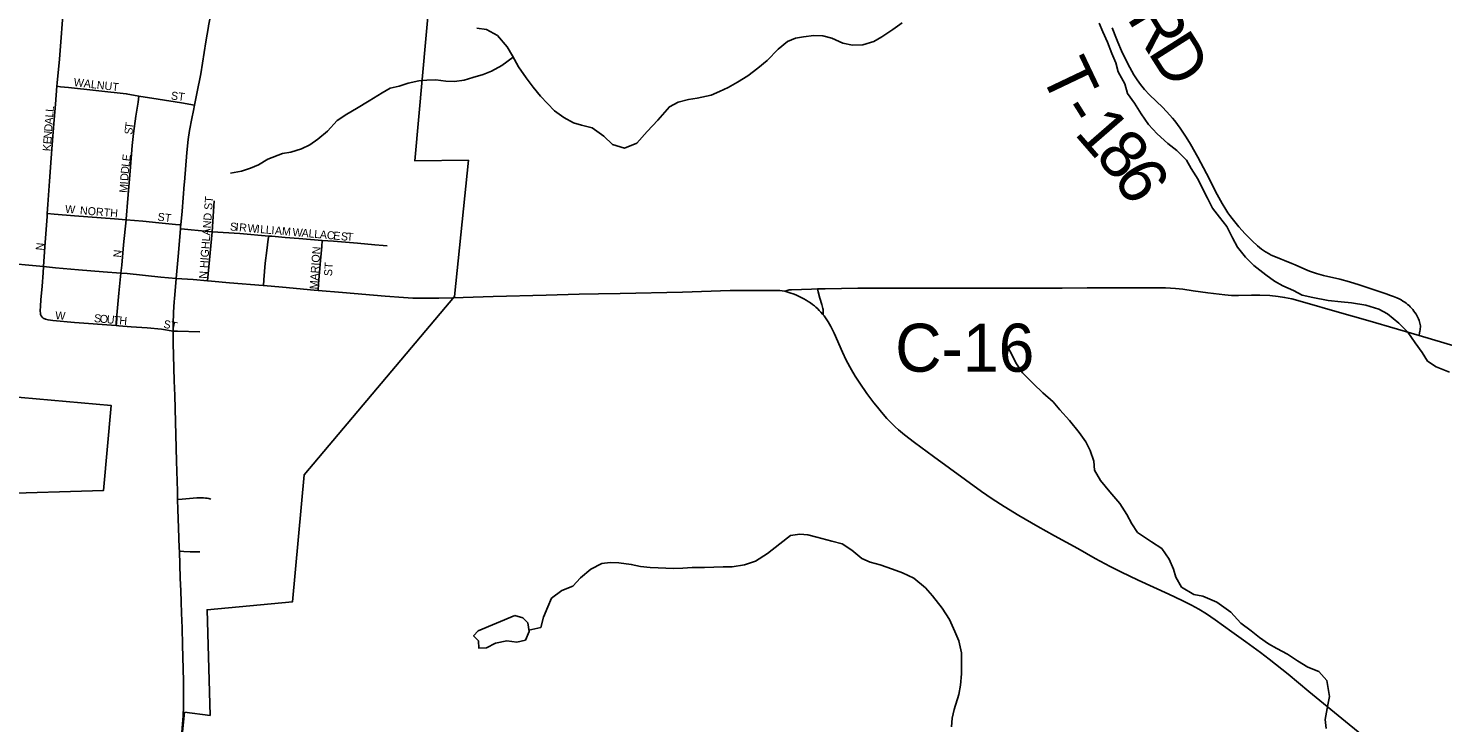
# Model space of a CAD drawing. Extents: x 1451455 to 1749751, y 218250 to 574981.
# Drawn here: x 1601082 to 1609917, y 315557 to 319894 of the extents above; entities that cross this region are included whole.
import ezdxf

# ---------------------------------------------------------------- set-up
doc = ezdxf.new("R2010")
doc.units = 0
for name, color, linetype in [('GM_X_City_Street', 7, 'Continuous'), ('GM_X_City_Street_Text', 7, 'Continuous'), ('GM_X_Corporation', 7, 'Continuous'), ('GM_X_County_Road', 7, 'Continuous'), ('GM_X_County_Road_Text', 7, 'Continuous'), ('GM_X_Minor_Lake', 7, 'Continuous'), ('GM_X_Minor_River', 7, 'Continuous'), ('GM_X_State_Route', 7, 'Continuous'), ('GM_X_Township_Road', 7, 'Continuous'), ('GM_X_Township_Road_Text', 7, 'Continuous'), ('GM_X_US_Route', 7, 'Continuous')]:
    doc.layers.add(name, color=color, linetype=linetype)

msp = doc.modelspace()

# ---------------------------------------------------------------- linework, layer by layer
at = {"layer": 'GM_X_City_Street'}
for points in [[(1601260.7, 319531.9), (1601262.4, 319553.9), (1601276.3, 319702.3), (1601303.8, 320055.2), (1601304.3, 320073.5)], [(1601200.4, 318737.8), (1601204.4, 318793.1), (1601213.7, 318940.3), (1601225, 319084.1), (1601231.1, 319165.9), (1601241.8, 319300), (1601252.3, 319420.9), (1601260.7, 319531.9)], [(1601260.7, 319531.9), (1601282.9, 319529.5), (1601331.8, 319524.3), (1601693, 319485.2), (1601772.9, 319469.7)], [(1601692, 318698.4), (1601692.4, 318702.3), (1601703.3, 318832.1), (1601717.9, 319001.6), (1601731, 319161.4), (1601738.7, 319236.3), (1601753.3, 319346.4), (1601767.2, 319433.7), (1601772.9, 319469.7)], [(1601772.9, 319469.7), (1601892.8, 319450.7), (1602038.4, 319427.9), (1602120.8, 319415.1)], [(1602230.9, 318622.8), (1602243.1, 318817.6)], [(1601176.6, 318405.7), (1601185.2, 318528.4), (1601199, 318717.9), (1601200.4, 318737.8)], [(1601200.4, 318737.8), (1601243.8, 318734.2), (1601369.4, 318723.7), (1601619.8, 318704.9), (1601692, 318698.4)], [(1601659.7, 318364.9), (1601663.6, 318398.3), (1601665.5, 318414.6), (1601676.1, 318541.6), (1601692, 318698.4)], [(1601692, 318698.4), (1601796.6, 318689), (1601897.2, 318679.5), (1602001.5, 318669.1), (1602033.6, 318665.9)], [(1602031.6, 318642.4), (1602057.4, 318640), (1602099.5, 318636.2), (1602230.9, 318622.8)], [(1602201.5, 318316.9), (1602230.9, 318622.8)], [(1602230.9, 318622.8), (1602402.2, 318612.1), (1602583.8, 318596.8)], [(1602550.5, 318287.8), (1602553.5, 318323.3), (1602562.1, 318427.6), (1602571.1, 318505.6), (1602581, 318576.9), (1602583.8, 318596.8)], [(1602583.8, 318596.8), (1602602.4, 318595.2), (1602687.3, 318588.6), (1602772.2, 318580.7), (1602917.9, 318569.4)], [(1602891.9, 318257.4), (1602895.2, 318297.2), (1602907.4, 318444.1), (1602914.8, 318532), (1602917.9, 318569.4)], [(1602917.9, 318569.4), (1602988.9, 318564), (1603088.8, 318556.1), (1603137.7, 318552.2), (1603245.4, 318541.8), (1603297.6, 318537.5), (1603323.7, 318535)], [(1601175, 318083.9), (1601167.6, 318090), (1601161.8, 318097.9), (1601158, 318106.9), (1601156.8, 318113.3), (1601155.9, 318129.3), (1601156.9, 318158.5), (1601160.1, 318197.7), (1601167.6, 318284.3), (1601173.7, 318366.9), (1601176.6, 318405.7)], [(1601630, 318037.4), (1601631.3, 318056.5), (1601633, 318079.5), (1601634.5, 318103), (1601647.3, 318240.2), (1601659.7, 318364.9)], [(1601175, 318083.9), (1601189.3, 318077.4), (1601205.1, 318073.2), (1601234, 318068.5), (1601370.7, 318056.1), (1601630, 318037.4)], [(1601630, 318037.4), (1601646.7, 318036.2), (1601724.9, 318030), (1601823.9, 318023.2), (1601912.9, 318014.4), (1601986.5, 318003.2)], [(1601986.5, 318003.2), (1602013.5, 318002.5), (1602152.3, 317999.1)], [(1602014.5, 316951.9), (1602042.4, 316954.1), (1602133.5, 316961.2), (1602163.2, 316961.8), (1602176, 316961.4), (1602189.5, 316960.4), (1602199.1, 316958.7), (1602209, 316956.8), (1602221.9, 316953.2)], [(1602025.4, 316628.3), (1602053.1, 316626.9), (1602092, 316625), (1602154, 316623.9)]]:
    msp.add_lwpolyline(points, dxfattribs=at)
at = {"layer": 'GM_X_Corporation'}
for points in [[(1600894.4, 321782.8), (1601586.6, 321717.6), (1602551.4, 321643.6), (1602650.6, 322065), (1604467.4, 321666.3), (1604443, 321472.2), (1604960, 321426.4), (1604865.9, 320543.7), (1603638.6, 320637.9), (1603496, 319066.6), (1603830.6, 319069.7), (1603743.1, 318219.8), (1602805, 317104.4), (1602731.4, 316312), (1602198.9, 316262.9), (1602217.2, 315602.4), (1602057.6, 315622.4), (1601937.9, 314443.3)], [(1600860.8, 316985.6), (1601552.2, 317007.5), (1601600.2, 317537.6), (1600567.3, 317630.6)]]:
    msp.add_lwpolyline(points, dxfattribs=at)
at = {"layer": 'GM_X_County_Road'}
for points in [[(1606012.1, 318266.4), (1606060.6, 318267.4), (1606263.9, 318270.1), (1606345.8, 318270.2), (1606503.2, 318271.4), (1606673.5, 318270.9), (1606808, 318271.4), (1606919.5, 318271.4), (1607080.2, 318271.8), (1607286.8, 318270.9), (1607539.3, 318271.9), (1607696.7, 318272.6), (1607824.7, 318273.5), (1607975.5, 318272.3), (1608116.4, 318272.5), (1608185.3, 318272.4), (1608216.9, 318271.2), (1608247.6, 318269.2), (1608293.3, 318264.4), (1608358.4, 318255.4), (1608449.3, 318242.4), (1608556.3, 318228.9), (1608598.6, 318226.1), (1608640.9, 318225.7), (1608722.8, 318228.1), (1608775.5, 318228.1), (1608837.9, 318225.1), (1608890.3, 318219.8), (1608929.2, 318213.5), (1608974.2, 318203.8), (1609056.4, 318181.4), (1609257.7, 318123.5), (1609450, 318068.8), (1609635.7, 318014.2), (1609769.9, 317974.6)], [(1605808.4, 318251.4), (1605822.9, 318257.1), (1605835.5, 318260.1), (1605849, 318261.6), (1605975.3, 318265.6), (1606012.1, 318266.4)], [(1606047, 318104.8), (1606047.7, 318121.9), (1606047.3, 318130), (1606046.3, 318138.1), (1606045, 318144.4), (1606043.4, 318151.9), (1606038.5, 318169.3), (1606026.8, 318209.1), (1606016.6, 318247.3), (1606012.1, 318266.4)], [(1609769.9, 317974.6), (1610000.7, 317906.4)]]:
    msp.add_lwpolyline(points, dxfattribs=at)
at = {"layer": 'GM_X_Minor_Lake'}
for points in [[(1603892, 316130), (1603863.6, 316100.3), (1603893.2, 316067.9), (1603896.7, 316021.8), (1603944.7, 316025.2), (1604001.2, 316054.5), (1604071.4, 316067.5), (1604133.4, 316060.7), (1604187.5, 316072), (1604210.3, 316127.8), (1604202.9, 316179.9), (1604171.3, 316212.4), (1604121.4, 316227.1)], [(1604121.4, 316227.1), (1603892, 316130)]]:
    msp.add_lwpolyline(points, dxfattribs=at)
at = {"layer": 'GM_X_Minor_River'}
for points in [[(1606540.4, 319927.6), (1606481.8, 319886.3), (1606413.2, 319841.1), (1606362.8, 319811.8), (1606294.4, 319790.7), (1606230.4, 319789.5), (1606170.4, 319800.3), (1606100.8, 319833.3), (1606044.9, 319848), (1605988.9, 319848.8), (1605924.7, 319841.6), (1605874.6, 319832.3), (1605824.3, 319810.9), (1605765.6, 319763.6), (1605696.7, 319692.5), (1605638, 319645.2), (1605577.4, 319597.9), (1605512.8, 319556.8), (1605454.3, 319523.5), (1605399.9, 319500.2), (1605347.6, 319476.8), (1605259.3, 319458), (1605205.1, 319448.7), (1605140.9, 319433.5), (1605086.5, 319404.2), (1605015.3, 319321.1), (1604948.4, 319249.8), (1604883.4, 319176.6), (1604806.9, 319145.6), (1604731.2, 319168.6), (1604677.8, 319221.4), (1604604.4, 319272.5), (1604538.5, 319289.3), (1604486.6, 319304), (1604427, 319336.9), (1604369.5, 319379.7), (1604280.6, 319471), (1604235.2, 319525.7), (1604191.9, 319584.3), (1604144.7, 319653), (1604105.6, 319721.6), (1604072.3, 319778.1), (1604013.1, 319849), (1603943.5, 319886), (1603883.6, 319894.8)], [(1609960, 317747.5), (1609876.3, 317780.7), (1609822.7, 317815.4), (1609789.4, 317869.9), (1609746.1, 317930.6), (1609698.9, 317995.3), (1609643.5, 318052.1), (1609572.2, 318111.1), (1609518.5, 318139.9), (1609436.8, 318165), (1609346.9, 318180.2), (1609282.9, 318185), (1609200.9, 318194.1), (1609105.1, 318213.4), (1609039.2, 318228.3), (1608985.5, 318257.1), (1608917.8, 318286), (1608866.1, 318314.7), (1608812.6, 318353.5), (1608737.3, 318412.6), (1608685.9, 318465.3), (1608634.6, 318528.1), (1608605.3, 318586.5), (1608568.2, 318657.1), (1608522.9, 318713.8), (1608479.5, 318770.4), (1608448.3, 318832.9), (1608417, 318893.4), (1608389.7, 318949.8), (1608346.5, 319018.5), (1608317.2, 319071), (1608255.9, 319131.8), (1608200.4, 319174.6), (1608133.1, 319235.6), (1608079.8, 319292.4), (1608034.6, 319359), (1607991.4, 319425.7), (1607948.1, 319486.3), (1607930.8, 319546.7), (1607889.8, 319623.3), (1607876.4, 319677.5), (1607851.2, 319736), (1607824.1, 319808.4), (1607794.8, 319872.9), (1607771.5, 319925.2)], [(1604109.7, 319714.3), (1604038.8, 319662.4), (1603974.3, 319627.2), (1603923.9, 319605.9), (1603857.6, 319586.7), (1603805.4, 319569.4), (1603743.2, 319562.2), (1603689.2, 319563), (1603627.2, 319571.8), (1603571.2, 319570.5), (1603521.1, 319565.2), (1603454.8, 319552), (1603398.5, 319532.8), (1603342.3, 319519.5), (1603291.9, 319492.1), (1603211.2, 319441.1), (1603132.6, 319394.1), (1603072, 319358.9), (1603011.5, 319317.6), (1602950.6, 319252.4), (1602889.9, 319201.1), (1602839.4, 319165.7), (1602789.1, 319142.4), (1602722.7, 319121.2), (1602668.6, 319111.9), (1602578, 319077.1), (1602519.5, 319041.8), (1602469.2, 319020.5), (1602412.9, 319001.2), (1602344.7, 318990.1)], [(1609189.1, 315521), (1609183.8, 315577.1), (1609199, 315669), (1609209.7, 315721), (1609192.9, 315821.3), (1609143.6, 315876), (1609075.9, 315905), (1609010.3, 315943.9), (1608948.8, 315984.8), (1608881.1, 316019.7), (1608829.5, 316050.4), (1608773.9, 316089.2), (1608720.4, 316130), (1608657, 316178.9), (1608593.8, 316247.8), (1608506.5, 316311), (1608418.9, 316348.2), (1608362.9, 316357), (1608285.5, 316404.1), (1608250.2, 316466.6), (1608234.8, 316516.9), (1608209.6, 316579.3), (1608162.4, 316646), (1608098.9, 316686.9), (1608011.5, 316746.1), (1607976.2, 316798.7), (1607944.9, 316857.1), (1607899.7, 316925.8), (1607838.6, 316998.7), (1607779.4, 317069.6), (1607742.2, 317134.2), (1607738.9, 317190.3), (1607715.7, 317256.7), (1607688.4, 317311.1), (1607647.1, 317369.7), (1607586, 317444.6), (1607524.8, 317511.5), (1607483.4, 317562.1), (1607420, 317617), (1607360.7, 317673.9), (1607291.5, 317742.9), (1607250.2, 317805.5), (1607219, 317870), (1607183.7, 317926.6)], [(1606849.1, 315532), (1606853.8, 315586), (1606866.5, 315639.9), (1606893.7, 315733.7), (1606904.5, 315791.6), (1606911.4, 315861.6), (1606912.2, 315925.7), (1606911, 315993.8), (1606894, 316068.1), (1606870.7, 316126.5), (1606835.6, 316201), (1606790.4, 316271.7), (1606729.4, 316348.6), (1606686, 316399.3), (1606612.7, 316460.3), (1606543, 316493.3), (1606481.2, 316516.1), (1606403.5, 316543.2), (1606341.7, 316560), (1606287.9, 316582.8), (1606226.5, 316635.7), (1606165, 316674.5), (1606101.1, 316691.4), (1606007.3, 316716.7), (1605951.5, 316731.4), (1605901.5, 316734.1), (1605843.3, 316726.9), (1605776.6, 316673.7), (1605699.8, 316614.6), (1605625.1, 316565.5), (1605554.7, 316542.5), (1605478.5, 316531.5), (1605422.5, 316530.2), (1605306.3, 316525.7), (1605228.2, 316526.8), (1605170.1, 316521.5), (1605112, 316520.3), (1605016, 316523.6), (1604966, 316526.2), (1604906, 316533), (1604848.1, 316545.8), (1604770.2, 316554.9), (1604716.2, 316557.6), (1604664, 316552.3), (1604595.5, 316515.1), (1604530.8, 316461.9), (1604484.1, 316410.5), (1604413.7, 316383.4), (1604351, 316334.2), (1604326.3, 316280.4), (1604299.5, 316216.7), (1604282.6, 316150.8), (1604209.3, 316134.8)]]:
    msp.add_lwpolyline(points, dxfattribs=at)
at = {"layer": 'GM_X_State_Route'}
for points in [[(1600526.3, 318463.6), (1600663.2, 318451.9), (1600901.7, 318430.4), (1601176.6, 318405.7), (1601251.3, 318398.9), (1601395.1, 318386), (1601548.7, 318373.9), (1601659.7, 318364.9)], [(1601659.7, 318364.9), (1601698.6, 318361.8), (1601910, 318340.4), (1602005.4, 318331.4), (1602112.1, 318324.8), (1602201.5, 318316.9), (1602225.4, 318314.8), (1602339, 318304.8), (1602547.9, 318288.1), (1602550.5, 318287.8)], [(1602550.5, 318287.8), (1602668.6, 318277.3), (1602867.7, 318259.4), (1602891.9, 318257.4), (1603043.4, 318244.5), (1603310.4, 318220.2), (1603425, 318212), (1603484.1, 318209.4), (1603561.2, 318208.3), (1603645.8, 318209.4)], [(1603645.8, 318209.4), (1603736.6, 318211.7), (1603985, 318218.2), (1604316, 318228.3), (1604522.4, 318232.9), (1604643.8, 318235.7), (1604778.3, 318238.1), (1605168.6, 318247), (1605467, 318256.7), (1605762.4, 318257.2), (1605777.4, 318256.7), (1605790.9, 318254.8), (1605808.4, 318251.4), (1605827.2, 318246.6), (1605845, 318240.6), (1605859.2, 318235.6), (1605876.7, 318228.6), (1605892.9, 318221.7), (1605909.7, 318213.7), (1605925.5, 318205.5), (1605940.6, 318197), (1605954.1, 318188.6), (1605967.9, 318179.2), (1605981.1, 318169.3), (1605992.4, 318160.5), (1606001.6, 318152.4), (1606013, 318142), (1606023.2, 318131.7), (1606033.6, 318120.8), (1606043.2, 318109.6), (1606047, 318104.8), (1606052.7, 318097.6), (1606061.6, 318086), (1606070.3, 318073.9), (1606078.2, 318061.2), (1606094.1, 318032), (1606114.9, 317989.5), (1606167.6, 317870.8), (1606191.7, 317820.7), (1606224, 317760.2), (1606247.1, 317720.8), (1606275.5, 317676.9), (1606320.5, 317612.6), (1606363.7, 317555), (1606385.7, 317527.3), (1606411.1, 317496.6), (1606445.6, 317457.3), (1606481.7, 317419.6), (1606497.3, 317404.4), (1606517.3, 317386.1), (1606554.7, 317354.6), (1606616.9, 317306.7), (1606735.8, 317219.5), (1607035.6, 317001.8), (1607102.8, 316954.8), (1607177, 316907.1), (1607269.3, 316850.9), (1607388.3, 316781.7), (1607491.3, 316724.3), (1607638.1, 316644.2), (1607746.8, 316583.2), (1607839.2, 316533.7), (1607906.5, 316499.9), (1608016, 316447.9), (1608207, 316360.8), (1608289.9, 316321.1), (1608348.4, 316291.1), (1608394.4, 316265.3), (1608442.1, 316236.1), (1608496.8, 316199.7), (1608601, 316125.5), (1608688.5, 316061.9), (1608778.4, 315996.1), (1608833.3, 315954.4), (1608951.4, 315860.6), (1609017.4, 315806.6), (1609080.5, 315752.6), (1609288.1, 315583.6), (1609412.8, 315482.2)]]:
    msp.add_lwpolyline(points, dxfattribs=at)
at = {"layer": 'GM_X_Township_Road'}
for points in [[(1609570.8, 318233.1), (1609501.5, 318257.5), (1609395.6, 318292.5), (1609335.9, 318310.1), (1609275.7, 318326.3), (1609173.5, 318350.1), (1609129.4, 318362.7), (1609086.1, 318377.9), (1609055.8, 318390.4), (1608995.8, 318417), (1608974.6, 318425.9), (1608929.2, 318444.8), (1608907.9, 318453.2), (1608861.9, 318470.8), (1608846.7, 318477.5), (1608832.3, 318484.9), (1608809.6, 318498), (1608797.6, 318505.8), (1608785.5, 318514.9), (1608760.1, 318535.7), (1608726.6, 318567.1), (1608682.8, 318611.5), (1608643.1, 318655.1), (1608617.8, 318685.4), (1608602.3, 318705.4), (1608588.2, 318724.6), (1608575.8, 318742.3), (1608562.3, 318762.5), (1608540.3, 318799), (1608509.3, 318856.8), (1608441.9, 318988.1), (1608387.7, 319089.3), (1608342.8, 319169.5), (1608315.6, 319214.3), (1608276.6, 319271.1), (1608243, 319315.5), (1608228.6, 319333.4), (1608213.5, 319350.7), (1608168.9, 319398.8), (1608086.8, 319479.2), (1608055.5, 319512.7), (1608030, 319542.3), (1608008.8, 319571.3), (1607988, 319603.9), (1607962.3, 319649.1), (1607937.8, 319697.5), (1607911.2, 319753.9), (1607887.8, 319808.1), (1607879.2, 319829.3), (1607852, 319896.1)], [(1609769.9, 317974.6), (1609773.3, 317991.4), (1609775.4, 318001.6), (1609776.8, 318011.4), (1609777.5, 318019.9), (1609778, 318028.1), (1609777.8, 318036.4), (1609776.8, 318044.4), (1609775.4, 318052.2), (1609773.2, 318060.4), (1609769.9, 318069.3), (1609766.3, 318078.8), (1609762.3, 318087.6), (1609757.7, 318096.5), (1609751.3, 318108.2), (1609744.3, 318119), (1609738, 318128.1), (1609730.6, 318137.5), (1609723.3, 318146), (1609715.1, 318154.4), (1609707, 318162), (1609698.1, 318169.8), (1609689.1, 318176.8), (1609679.8, 318183.6), (1609669, 318190.6), (1609657.4, 318197.3), (1609644.7, 318204.1), (1609630.9, 318210.1), (1609609.3, 318218.9), (1609585, 318228), (1609570.8, 318233.1)]]:
    msp.add_lwpolyline(points, dxfattribs=at)
at = {"layer": 'GM_X_US_Route'}
for points in [[(1602056.2, 318918.3), (1602057.4, 318932.3), (1602071.9, 319118.8), (1602081, 319200.4), (1602089.5, 319255.7), (1602103.8, 319329.9), (1602114.2, 319381.4), (1602120.8, 319415.1), (1602134.9, 319487.7), (1602158.6, 319610), (1602191.6, 319810.6), (1602207.1, 319904.6), (1602208.2, 319910.4), (1602252.4, 320147.8), (1602259.4, 320185.3), (1602277.8, 320283.6), (1602296.9, 320385.4), (1602324.4, 320527.1), (1602334.5, 320581.1), (1602357.1, 320701.3), (1602382.1, 320830.1), (1602412.3, 321007.3)], [(1602005.4, 318331.4), (1602017.7, 318468.3), (1602031.6, 318642.4), (1602033.1, 318661.2), (1602033.6, 318665.9), (1602042.1, 318752.5), (1602056.2, 318918.3)], [(1601992.8, 318188.7), (1601993.9, 318204.1), (1602005.4, 318331.4)], [(1602048.9, 315600.5), (1602051, 315657.6), (1602052.1, 315729.6), (1602050.9, 315817.9), (1602044.3, 316040.8), (1602042, 316149), (1602038.7, 316240.7), (1602036.3, 316312.8), (1602034.1, 316381.6), (1602030.6, 316460.2), (1602025.4, 316628.3), (1602024.8, 316646.9), (1602020, 316774.7), (1602016.4, 316889.4), (1602014.5, 316951.9), (1602012.9, 317004.1), (1602008.3, 317190.9), (1601996.6, 317600.4), (1601993.4, 317692.5), (1601989.3, 317853.3), (1601989.5, 317862.5), (1601987.2, 317915.9), (1601986.5, 318003.2), (1601986.1, 318046.3), (1601988.2, 318118.9), (1601992.8, 318188.7)], [(1601978.7, 314803.6), (1602007.8, 315108.2), (1602025, 315307.6), (1602036.6, 315445), (1602048.9, 315600.5)]]:
    msp.add_lwpolyline(points, dxfattribs=at)

# ---------------------------------------------------------------- texts
at = {"layer": 'GM_X_City_Street_Text'}
for s, rotation, p in [('WALNUT', 353.34575, (1601363.3, 319533.9)), ('ST', 352.87835, (1601970.6, 319450.3)), ('A', 85.73065, (1601233.3, 319291.6)), ('L', 85.72765, (1601236.6, 319335.4)), ('L', 85.65158, (1601239.2, 319370.5)), ('N', 85.71193, (1601226.7, 319203.8)), ('D', 85.73065, (1601230, 319247.7)), ('S', 83.56628, (1601731.1, 319228.2)), ('T', 82.49201, (1601735, 319263)), ('K', 85.73373, (1601220.8, 319124.8)), ('E', 85.73434, (1601224.1, 319168.7)), ('E', 82.57507, (1601717, 319061.5)), ('D', 86.26006, (1601705.3, 318939.8)), ('D', 84.19806, (1601708.1, 318983.2)), ('L', 82.6581, (1601712.5, 319026.6)), ('M', 86.26346, (1601700.4, 318865.1)), ('I', 86.26645, (1601703.9, 318917.8)), ('N HIGHLAND ST', 85.6847, (1602197.6, 318328.4)), ('W', 355.60387, (1601310.1, 318741.9)), ('NORTH', 355.23674, (1601402.6, 318733.1)), ('ST', 352.8733, (1601887, 318693.5)), ('S', 354.99357, (1602340.1, 318631.9)), ('I', 355.00454, (1602375.2, 318628.8)), ('R', 354.99028, (1602397.1, 318626.9)), ('W', 354.99417, (1602449.7, 318622.3)), ('I', 355.00454, (1602506.7, 318617.3)), ('L', 354.99357, (1602528.6, 318615.4)), ('L', 354.99305, (1602563.6, 318612.3)), ('I', 354.98956, (1602598.7, 318609.2)), ('A', 354.99221, (1602620.6, 318607.3)), ('M', 354.98731, (1602664.4, 318603.5)), ('W', 354.99932, (1602730.2, 318597.7)), ('A', 354.98765, (1602787.2, 318592.7)), ('L', 354.99305, (1602831, 318588.9)), ('L', 354.99305, (1602866.1, 318585.8)), ('A', 355.00408, (1602901.1, 318582.7)), ('C', 354.99028, (1602945, 318578.9)), ('E', 354.99818, (1602984.4, 318575.5)), ('N', 84.29264, (1601176.9, 318504.7)), ('S', 354.99818, (1603032.6, 318571.2)), ('T', 357.11199, (1603069.7, 318568)), ('N', 84.29264, (1601660.9, 318460.7)), ('MARION', 85.91271, (1602888.4, 318262.4)), ('ST', 86.41218, (1602978.7, 318344.9)), ('W', 355.59551, (1601248.5, 318077.5)), ('S', 354.66458, (1601490.7, 318059.9)), ('O', 354.65914, (1601525.8, 318056.6)), ('U', 354.65914, (1601569.6, 318052.5)), ('T', 354.66389, (1601613.4, 318048.4)), ('H', 354.66565, (1601648.4, 318045.2)), ('ST', 348.69147, (1601922.9, 318024.6))]:
    msp.add_text(s, height=50, rotation=rotation, dxfattribs=at).set_placement(p)
at = {"layer": 'GM_X_County_Road_Text'}
msp.add_text('C-16', height=300, rotation=0.00001, dxfattribs=at).set_placement((1606497, 317749.3))
at = {"layer": 'GM_X_Township_Road_Text'}
for s, rotation, p in [('R', 301.44112, (1607940.7, 319959.9)), ('D', 302.3695, (1608072, 319745.2)), ('T', 295.44953, (1607400.3, 319616.8)), ('-', 302.18615, (1607515.3, 319380.5)), ('1', 310.9943, (1607610.9, 319235.9)), ('8', 312.67046, (1607738.5, 319089.2)), ('6', 300.44524, (1607853.6, 318966.9))]:
    msp.add_text(s, height=300, rotation=rotation, dxfattribs=at).set_placement(p)

doc.saveas('drawing.dxf')
